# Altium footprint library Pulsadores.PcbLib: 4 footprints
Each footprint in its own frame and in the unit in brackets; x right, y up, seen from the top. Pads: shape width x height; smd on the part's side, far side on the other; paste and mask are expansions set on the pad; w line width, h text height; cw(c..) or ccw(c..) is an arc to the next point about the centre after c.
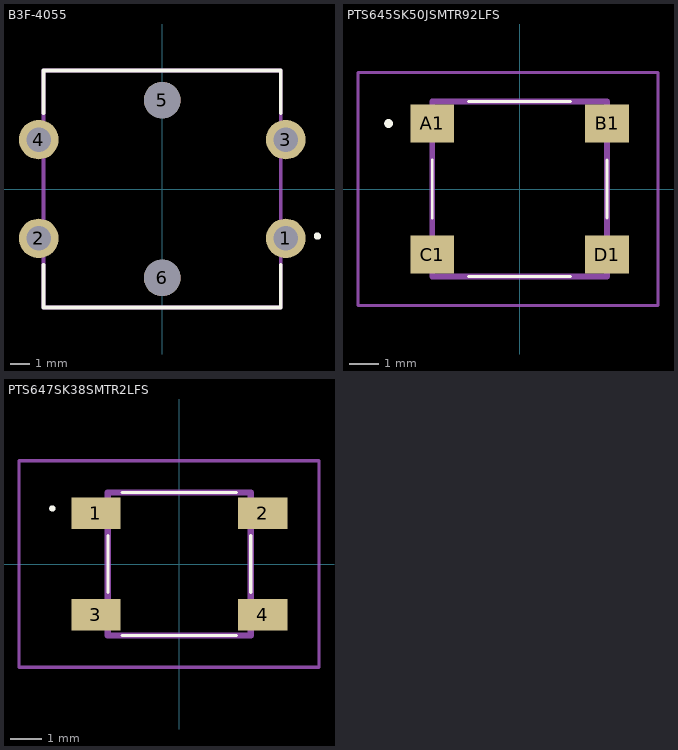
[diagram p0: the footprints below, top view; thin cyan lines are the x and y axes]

## B3F-4055 [mm]
pads (6):
  round 2 hole 1.25: 1(6.25,-2.5) 2(-6.25,-2.5) 3(6.25,2.5) 4(-6.25,2.5)
  round 1.85 hole 1.85 unplated: 5(0,4.5) 6(0,-4.5)
Top Overlay:
  circle w0.2: c7.855,-2.384 r0.082
  lines w0.2: -6,-3.849 -6,-6 6,-6 6,-3.849 ; -6,3.849 -6,6 6,6 6,3.849
Mechanical 13:
  lines w0.2: -6,-6 -6,6 6,6 6,-6 -6,-6
3D body "B3F-4055.stp": height 7.3, standoff -3.5, extent -6.9,-6.05 6.9,6.05

## PCBComponent_1 [mm]

## PTS645SK50JSMTR92LFS [mm]
pads (4):
  rect 1.5x1.3 smd: A1(-3,2.25) B1(3,2.25) C1(-3,-2.25) D1(3,-2.25)
Top Overlay:
  lines w0.1: -3,-1 -3,1 -3,-1 ; -1.75,-3 1.75,-3 -1.75,-3 ; -1.75,3 1.75,3 -1.75,3 ; 3,-1 3,1 3,-1
  lines w0.2: -4.5,2.2 cw(c-4.5,2.25) -4.5,2.3 ; -4.5,2.2 ccw(c-4.5,2.25) -4.5,2.3 ; -4.5,2.2 cw(c-4.5,2.25) -4.5,2.3
Mechanical 13:
  lines w0.2: -3,-3 -3,3 3,3 3,-3 -3,-3
Mechanical 15:
  lines w0.1: -5.55,-4 -5.55,4 4.75,4 4.75,-4 -5.55,-4
3D body "PTS645SK50JSMTR92_LFS.stp": height 4.84, standoff 0, extent -3.24,-3 3.44,3

## PTS647SK38SMTR2LFS [mm]
pads (4):
  rect 1.55x1 smd: 1(-2.625,1.6) 2(2.625,1.6) 3(-2.625,-1.6) 4(2.625,-1.6)
Top Overlay:
  lines w0.1: -2.25,-0.9 -2.25,0.9 ; -1.8,-2.25 1.8,-2.25 ; -1.8,2.25 1.8,2.25 ; 2.25,-0.9 2.25,0.9 ; -4,1.7 ccw(c-4,1.75) -4,1.8 ccw(c-4,1.75) -4,1.7
Mechanical 13:
  lines w0.2: -2.25,-2.25 -2.25,2.25 2.25,2.25 2.25,-2.25 -2.25,-2.25
Mechanical 15:
  lines w0.1: -5.05,-3.25 -5.05,3.25 4.4,3.25 4.4,-3.25 -5.05,-3.25
3D body "PTS647SK38SMTR2LFS.stp": height 3.8, standoff 0, extent -3.58,-2.25 2.92,2.25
